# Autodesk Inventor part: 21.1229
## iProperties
IsCustomPart: 1
Created: 2006-02
Part Number: 21.1229
Material: Steel, Mild
Description: M4X12 SHCS ZINC PLATED DIN 7984
Document SubType Name: Modeling
Standard: DIN 7984
Designer: Andy Moles
Standards Organization: DIN
Language: en-US
Size Designation: M4 x 12
Categories: <MemberInstance><Categories><Category DisplayName="Fasteners" InternalName="e4da775c-781d-43d5-af7c-5136215cf5a6" Mnemonic="FSTN"><Category DisplayName="Bolts"
Density: 7.86 g/cm^3
Mass: 1.90624 g
Surface Area: 3.03485 cm^2
Volume: 0.242524 cm^3
Author: Andy Moles
Title: M4x12 SHCS ZINC PLATED
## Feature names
1. Body [Revolution]
2. Slot [Extrusion]
3. Fillet1
4. Chamfer1
